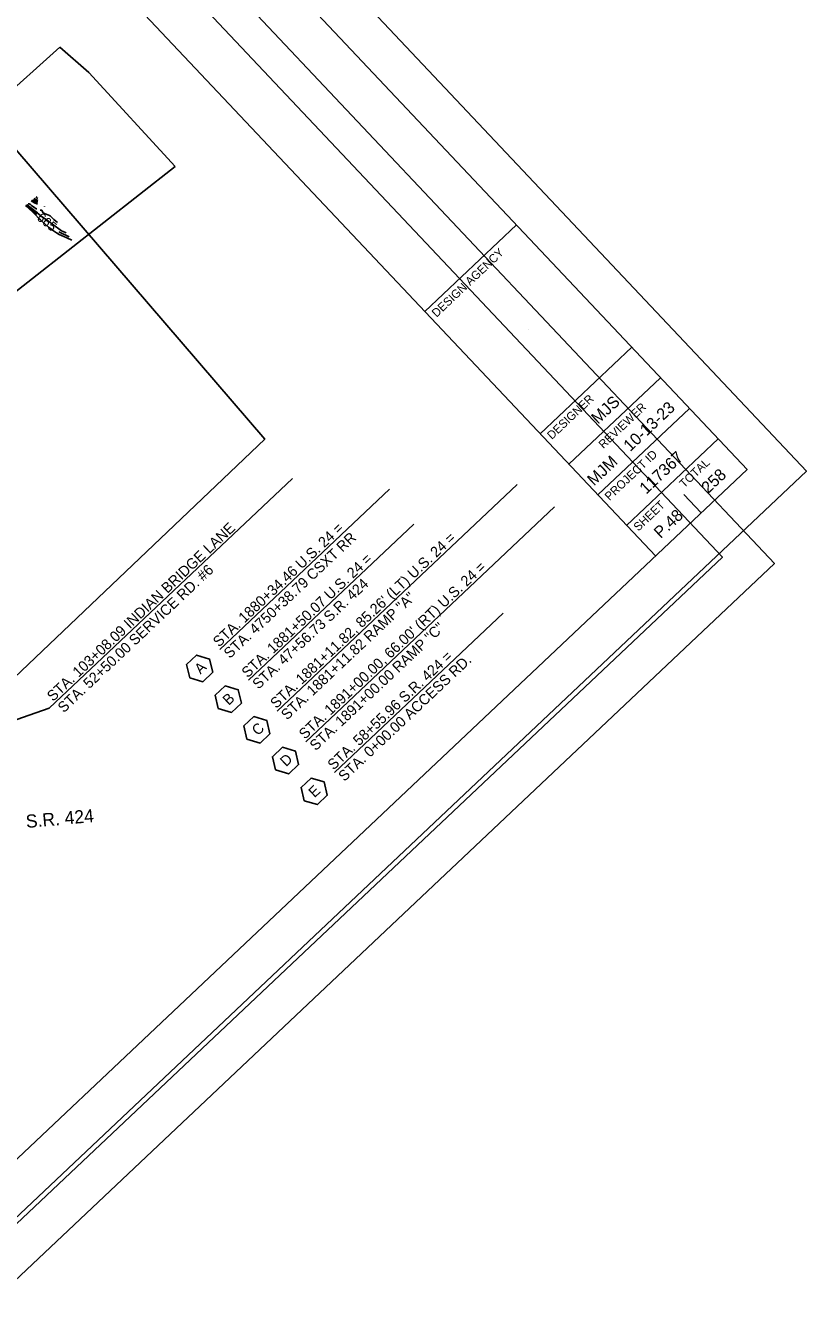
# Model space of a CAD drawing. Extents: x -291892836 to 2945206, y -477993085 to 1832792.
# Drawn here: x 1854368 to 1857157, y 542208 to 546767 of the extents above; entities that cross this region are included whole.
import ezdxf

# ---------------------------------------------------------------- set-up
doc = ezdxf.new("R2010")
doc.units = 0
for name, color, linetype in [('DT_X_Contour_Minor', 7, 'Continuous'), ('DT_X_Terrain_Ground_Line', 7, 'Continuous'), ('Level 40', 7, 'Continuous'), ('Level 63', 7, 'Continuous'), ('SC_Scratch1', 7, 'Continuous'), ('SH_Border', 7, 'Continuous'), ('SH_Cut_Line', 7, 'Continuous'), ('SH_Data', 7, 'Continuous')]:
    doc.layers.add(name, color=color, linetype=linetype)

msp = doc.modelspace()

# ---------------------------------------------------------------- linework, layer by layer
at = {"layer": 'DT_X_Contour_Minor'}
for points in [[(1854411.9, 546140), (1854408.4, 546141.8), (1854400.5, 546146.4), (1854397.6, 546148.2)], [(1854412.1, 546142), (1854407.6, 546144.3), (1854399.3, 546149.6)], [(1854412.3, 546148.8), (1854404.4, 546153.8)], [(1854408.1, 546153.9), (1854406.1, 546155.2)], [(1854368.6, 546124.3), (1854373.9, 546119.7), (1854374.6, 546118.7), (1854380.9, 546112.7), (1854394.5, 546100.4), (1854403.2, 546091.5), (1854416.1, 546077.9), (1854421.2, 546073.2), (1854425.6, 546069.3), (1854438.4, 546057.1), (1854450.1, 546047.3), (1854457.2, 546041.8), (1854467.9, 546033.9), (1854479.1, 546026.7), (1854488.5, 546021.3), (1854504.9, 546013.3), (1854515.5, 546008.6), (1854533.8, 546000.8)], [(1854371.9, 546127.1), (1854373.8, 546125.2), (1854376, 546122.1), (1854377.6, 546120), (1854381.4, 546116.4), (1854388.8, 546110.4), (1854398, 546103), (1854404.6, 546096.9), (1854408.8, 546092.7)], [(1854374.9, 546129.5), (1854377.9, 546124.9), (1854380.1, 546121.6), (1854385.5, 546117.2), (1854410.6, 546097.6), (1854414.5, 546094), (1854424.4, 546086.8), (1854447.1, 546070.6), (1854469.4, 546054.1), (1854492, 546037.6), (1854497.2, 546033.9), (1854502, 546031.4), (1854512.7, 546026.5)], [(1854379.4, 546133.2), (1854380.4, 546131.9), (1854381.7, 546130.8), (1854385.6, 546128.3), (1854390, 546124.4), (1854394.7, 546120.8), (1854400.4, 546116.6), (1854406.2, 546113), (1854408.5, 546111.9)], [(1854410.6, 546129.1), (1854399.9, 546133.9), (1854392.3, 546138.1), (1854388.3, 546140.5)], [(1854410.8, 546131), (1854408.3, 546132.1), (1854402.2, 546135.1), (1854389.9, 546141.8)], [(1854411, 546132.7), (1854404.6, 546135.5), (1854401.9, 546136.9), (1854391.5, 546143.1)], [(1854411.7, 546138.2), (1854407.1, 546140.3), (1854400.8, 546144), (1854396.1, 546147)], [(1854420.9, 546108.2), (1854426, 546107.1), (1854427.7, 546105.8), (1854428.5, 546101.2), (1854430.8, 546098.4), (1854436.1, 546095.5), (1854453.7, 546089), (1854456.3, 546087.4), (1854458.2, 546085.6), (1854464.4, 546078.7), (1854469.2, 546074.4), (1854476.9, 546067.8), (1854482.7, 546063.1)], [(1854435.9, 546120.1), (1854435.5, 546120.2)], [(1854487, 546030.7), (1854524.3, 546012.3)]]:
    msp.add_lwpolyline(points, dxfattribs=at)
at = {"layer": 'Level 40'}
for p, q in [((1854452.6, 544330.3), (1855321.3, 545150.2)), ((1855062, 544539.1), (1855668.5, 545111.5)), ((1855266.7, 544319.7), (1856123.7, 545128.6)), ((1855369, 544210), (1856257.2, 545048.3)), ((1855164.3, 544429.4), (1855754.5, 544986.4)), ((1855471.3, 544100.3), (1856073.7, 544668.9)), ((1854086.6, 544201.5), (1854452.6, 544330.3))]:
    msp.add_line(p, q, dxfattribs=at)
for points in [[(1854954.4, 544438.3), (1854943.1, 544485.7), (1854978.6, 544519.2), (1855025.3, 544505.2), (1855036.5, 544457.8), (1855001.1, 544424.3)], [(1855056.7, 544328.6), (1855045.5, 544376), (1855080.9, 544409.5), (1855127.6, 544395.5), (1855138.9, 544348.1), (1855103.4, 544314.6)], [(1855159, 544218.9), (1855147.8, 544266.4), (1855183.2, 544299.8), (1855229.9, 544285.9), (1855241.2, 544238.4), (1855205.7, 544205)], [(1855261.3, 544109.2), (1855250.1, 544156.7), (1855285.5, 544190.1), (1855332.3, 544176.2), (1855343.5, 544128.7), (1855308, 544095.3)], [(1855363.7, 543999.6), (1855352.4, 544047), (1855387.9, 544080.5), (1855434.6, 544066.5), (1855445.8, 544019), (1855410.4, 543985.6)]]:
    msp.add_lwpolyline(points, close=True, dxfattribs=at)
at = {"layer": 'Level 63'}
for p, q in [((1854491, 546689.1), (1852771.6, 545150.8)), ((1854594, 546599.3), (1854491, 546689.1)), ((1854903.1, 546264), (1854594, 546599.3)), ((1853783, 545386.5), (1854903.1, 546264))]:
    msp.add_line(p, q, dxfattribs=at)
for points in [[(1845095.9, 542645), (1852513.2, 549645.6), (1857042.8, 544846.4), (1849625.5, 537845.8)], [(1849613.4, 538032.4), (1856856.7, 544868.7), (1852499.5, 549485.3), (1845256.2, 542648.9)]]:
    msp.add_lwpolyline(points, close=True, dxfattribs=at)
at = {"layer": 'SC_Scratch1'}
msp.add_lwpolyline([(1847508.1, 542206.7), (1846998.9, 543896.8), (1851573.8, 547209.2), (1853501.8, 547291.7), (1855222.4, 545290.6), (1854278.6, 544392.1), (1853736.4, 543286.9), (1848894.1, 540466.9), (1848705.9, 540646.3)], close=True, dxfattribs=at)
at = {"layer": 'SH_Border'}
for p, q in [((1856617.8, 544873.1), (1852293.6, 549454.7)), ((1855794.1, 545745.8), (1856121.4, 546054.7)), ((1856206, 545309.5), (1856533.2, 545618.4)), ((1856308.9, 545200.4), (1856636.2, 545509.3)), ((1856411.9, 545091.3), (1856739.1, 545400.2)), ((1856514.8, 544982.2), (1856842.1, 545291.1))]:
    msp.add_line(p, q, dxfattribs=at)
msp.add_lwpolyline([(1845639.3, 543174.3), (1852620.8, 549763.6), (1856945.1, 545182), (1849963.6, 538592.7)], close=True, dxfattribs=at)
at = {"layer": 'SH_Cut_Line'}
msp.add_lwpolyline([(1849739.3, 538174.8), (1857157.1, 545175.9), (1852627, 549975.7), (1845209.1, 542974.5)], close=True, dxfattribs=at)
at = {"layer": 'SH_Data'}
for p, q in [((1856163.7, 545682.1), (1856163.7, 545682.1)), ((1856781.4, 545027.6), (1856719.7, 545093)), ((1856663.6, 544988.5), (1856663.6, 544988.5))]:
    msp.add_line(p, q, dxfattribs=at)

# ---------------------------------------------------------------- texts
at = {"layer": 'DT_X_Terrain_Ground_Line'}
msp.add_text('665', height=33, rotation=320.9638, dxfattribs=at).set_placement((1854405.7, 546075.7))
at = {"layer": 'Level 40'}
for s, height, rotation, p in [('STA. 103+08.09 INDIAN BRIDGE LANE', 37.5, 43.3446, (1854466.3, 544351.9)), ('STA. 1880+34.46 U.S. 24 =', 37.5, 43.3446, (1855058.9, 544545.8)), ('STA. 4750+38.79 CSXT RR', 37.5, 43.3446, (1855097.5, 544504.9)), ("STA. 1881+11.82, 85.26' (LT) U.S. 24 =", 37.5, 43.3446, (1855263.6, 544326.4)), ('STA. 1881+50.07 U.S. 24 =', 37.5, 43.3446, (1855161.3, 544436.1)), ('STA. 52+50.00 SERVICE RD. #6', 37.5, 43.3446, (1854504.7, 544311.2)), ("STA. 1891+00.00, 66.00' (RT) U.S. 24 =", 37.5, 43.3446, (1855365.9, 544216.7)), ('STA. 47+56.73 S.R. 424', 37.5, 43.3446, (1855199.9, 544395.2)), ('STA. 1881+11.82 RAMP "A"', 37.5, 43.3446, (1855302.2, 544285.5)), ('STA. 1891+00.00 RAMP "C"', 37.5, 43.3446, (1855404.5, 544175.8)), ('STA. 58+55.96 S.R. 424 =', 37.5, 43.3446, (1855468.2, 544107)), ('STA. 0+00.00 ACCESS RD.', 37.5, 43.3446, (1855506.8, 544066.1)), ('A', 37.5, 43.3446, (1854993, 544449)), ('B', 37.5, 43.3446, (1855093.8, 544337.8)), ('C', 37.5, 43.3446, (1855197.7, 544229.6)), ('D', 37.5, 43.3446, (1855298.7, 544118.7)), ('E', 37.5, 43.3446, (1855400.2, 544008.2)), ('S.R. 424', 46.8, 5.0229, (1854371.3, 543902.1))]:
    msp.add_text(s, height=height, rotation=rotation, dxfattribs=at).set_placement(p)
at = {"layer": 'SH_Data'}
for s, height, p in [('DESIGN AGENCY', 30, (1855835.9, 545723.4)), ('DESIGNER', 30, (1856247.8, 545287.1)), ('MJS', 42, (1856412.5, 545341.5)), ('10-13-23', 42, (1856527.5, 545243.7)), ('REVIEWER', 30, (1856431.8, 545254.5)), ('PROJECT ID', 30, (1856453.7, 545068.9)), ('117367', 42, (1856584.8, 545091.6)), ('MJM', 42, (1856398, 545121.5)), ('TOTAL', 30, (1856720.3, 545114.2)), ('258', 42, (1856806, 545094.1)), ('SHEET', 30, (1856556.6, 544959.8)), ('P.48', 42, (1856636.1, 544933.7))]:
    msp.add_text(s, height=height, rotation=43.3446, dxfattribs=at).set_placement(p)

doc.saveas('drawing.dxf')
